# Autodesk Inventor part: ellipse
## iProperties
Created: 2006-06
Part Number: ellipse
Cost Center: 0,03 kg
Document SubType Name: Blech
Designer: wk
Authority: 28606,8 mm^3
Author: wk
SaveDate: 2006-06-29
SaveTime: 10:45
TotalMass: 0,03 kg
TotalVolume: 28606,8 mm^3
SM_Thickness: 2 mm
SM_Style: Standard
SM_Extents: N/A
SM_Extents_Width: 0,000 mm
SM_Extents_Length: 0,000 mm
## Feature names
1. Sweeping1
2. Extrusion1
